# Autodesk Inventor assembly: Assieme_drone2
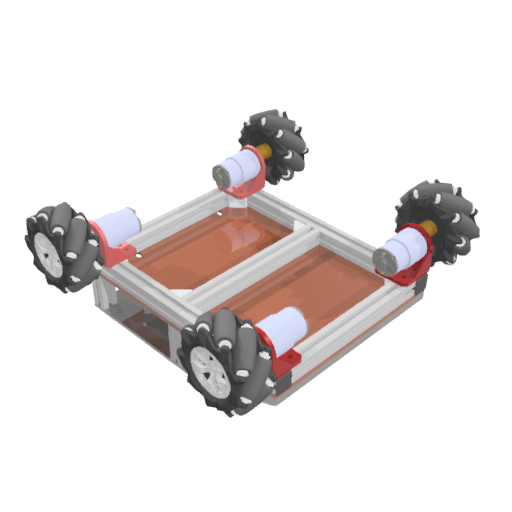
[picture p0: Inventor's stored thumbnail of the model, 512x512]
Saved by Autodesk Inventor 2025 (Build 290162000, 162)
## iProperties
Created: 2025-05
Part Number: Assieme_drone2
Document SubType Name: Assembly
Designer: R5800u
Author: R5800u
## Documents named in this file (28)
- C:\Users\R5800u\Desktop\drone_v2\Assieme_drone2.iam
- C:\Users\R5800u\Desktop\drone_v2\tslot-20x20-1.ipt
- C:\Users\R5800u\Desktop\drone_v2\tslot-20x20-1_MIR.ipt
- C:\Users\R5800u\Desktop\drone_v2\tslot-20x20-2.ipt
- C:\Users\R5800u\Desktop\drone_v2\SNSD20x20.ipt
- C:\Users\R5800u\Desktop\drone_v2\SNSD20x20_MIR.ipt
- C:\Users\R5800u\Desktop\drone_v2\tslot-20x20-3.ipt
- C:\Users\R5800u\Desktop\drone_v2\MM-JGB37 v4.ipt
- C:\Users\R5800u\Desktop\drone_v2\JGB37-520.ipt
- C:\Users\R5800u\Documents\Inventor\Content Center Files\R2025\it-IT\AS 1427(05)\AS 1427 - M4 x 10(5) II.ipt
- C:\Users\R5800u\Desktop\drone_v2\MM-JGB37 v4_MIR.ipt
- C:\Users\R5800u\Desktop\drone_v2\JGB37-520_MIR.ipt
- C:\Users\R5800u\Desktop\drone_v2\MM-JGB37 v4_MIR1.ipt
- C:\Users\R5800u\Desktop\drone_v2\JGB37-520_MIR1.ipt
- C:\Users\R5800u\Desktop\drone_v2\MM-JGB37 v4_MIR_MIR.ipt
- C:\Users\R5800u\Desktop\drone_v2\JGB37-520_MIR_MIR.ipt
- C:\Users\R5800u\Desktop\drone_v2\Mecanum wheel - right.ipt
- C:\Users\R5800u\Desktop\drone_v2\Mecanum wheel - left.ipt
- C:\Users\R5800u\Desktop\drone_v2\albero_ottonre_12x6.ipt
- C:\Users\R5800u\Desktop\drone_v2\tappi_tslot.ipt
- C:\Users\R5800u\Desktop\drone_v2\pianoA.ipt
- C:\Users\R5800u\Desktop\drone_v2\batteira_6V_LIFEPO4.ipt
- C:\Users\R5800u\Desktop\drone_v2\L298N.ipt
- C:\Users\R5800u\Desktop\drone_v2\ESP32-C3 Super Mini breakout expansion board module -Assembly.iam
- C:\Users\R5800u\Desktop\drone_v2\beetle ESP32-C3.iam
- C:\Users\R5800u\Desktop\jgb37\piano2.ipt
- C:\Users\R5800u\Desktop\jgb37\lato.ipt
- C:\Users\R5800u\Desktop\jgb37\lato2.ipt
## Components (48 placed, 27 different names)
1. tslot-20x20-1:1
2. tslot-20x20-1_MIR:1
3. tslot-20x20-2:1
4. tslot-20x20-2:2
5. SNSD20x20:1 — Allineato:14, Coincidente:22, Coincidente:23
6. SNSD20x20:2 — Allineato:13, Coincidente:20, Coincidente:21
7. SNSD20x20_MIR:1 — Allineato:15, Coincidente:24, Coincidente:27
8. SNSD20x20_MIR:2 — Allineato:16, Coincidente:25, Coincidente:26
9. tslot-20x20-2:3 — Allineato:17, Coincidente:28, Allineato:30, Allineato:32, Coincidente:30, Allineato:33, Coincidente:31
10. SNSD20x20_MIR:3 — Allineato:32, Coincidente:29, Coincidente:30
11. SNSD20x20:3 — Allineato:33, Coincidente:31, Coincidente:32
12. tslot-20x20-3:7 — Coincidente:70, Allineato:59, Allineato:62
13. MM-JGB37 v4:1
14. JGB37-520:1 — Rotazionale:1, Coincidente:43, Coincidente:44, Rigido:5
15. AS 1427 H - Metrico M4 x 10:1 — Coincidente:47
16. AS 1427 H - Metrico M4 x 10:2 — Coincidente:49
17. AS 1427 H - Metrico M4 x 10:3 — Rotazionale:2
18. MM-JGB37 v4_MIR:1 — Coincidente:50, Coincidente:51, Rotazionale:3, Coincidente:67, Allineato:53, Allineato:54
19. JGB37-520_MIR:1 — Coincidente:50, Coincidente:51, Rotazionale:3, Rigido:6
20. MM-JGB37 v4_MIR1:1 — Coincidente:52, Coincidente:53, Rotazionale:4, Coincidente:58, Coincidente:59, Allineato:48
21. JGB37-520_MIR1:1 — Coincidente:52, Coincidente:53, Rotazionale:4, Rigido:1
22. MM-JGB37 v4_MIR_MIR:1 — Coincidente:54, Coincidente:55, Rotazionale:5, Coincidente:68, Allineato:55, Allineato:56
23. JGB37-520_MIR_MIR:1 — Coincidente:54, Coincidente:55, Rotazionale:5, Rigido:7
24. Mecanum wheel - right:1 — Coincidente:60, Coincidente:64
25. Mecanum wheel - right:2 — Coincidente:62, Coincidente:63
26. Mecanum wheel - left:1 — Coincidente:56, Angolo:1, Coincidente:57
27. Mecanum wheel - left:2 — Coincidente:61, Coincidente:65
28. albero_ottonre_12x6:1 — Coincidente:56, Angolo:1, Coincidente:57, Rigido:1
29. albero_ottonre_12x6:2 — Coincidente:61, Coincidente:65, Rigido:5
30. albero_ottonre_12x6:3 — Coincidente:60, Coincidente:64, Rigido:6
31. albero_ottonre_12x6:4 — Coincidente:62, Coincidente:63, Rigido:7
32. tappi_tslot:1 — Allineato:51
33. tappi_tslot:2 — Rotazionale:6
34. pianoA:1 — Coincidente:69, Allineato:57, Allineato:58, Coincidente:70, Allineato:59, Allineato:60, Coincidente:71, Allineato:63, Coincidente:73, Rotazionale:7, Allineato:65, Coincidente:77, Allineato:83, Coincidente:78, Coincidente:79, Allineato:84, Allineato:85, Rotazionale:12, Rotazionale:13, Coincidente:81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
35. batteira_6V_LIFEPO4:1 — Coincidente:71, Allineato:63, Coincidente:72, Allineato:64
36. batteira_6V_LIFEPO4:2 — Coincidente:72, Allineato:64, Coincidente:73, Allineato:83, Coincidente:80
37. tslot-20x20-3:8 — Rotazionale:7, Allineato:65, Allineato:88
38. L298N:2 — Coincidente:79, Allineato:85, Allineato:86
39. L298N:3 — Coincidente:78, Allineato:84, Allineato:86, Allineato:87, Coincidente:80
40. ESP32-C3 Super Mini breakout expansion board module -Assembly:1 [sub-assembly] — Coincidente:77, Allineato:87
41. beetle ESP32-C3:1 [sub-assembly]
42. tslot-20x20-3:13 — Rotazionale:12
43. tslot-20x20-3:14 — Rotazionale:13
44. piano2:1 — Allineato:88, Allineato:89
45. lato:1 — Allineato:89, Allineato:91
46. lato2:1 — Coincidente:81, Allineato:90, Allineato:91
47. tappi_tslot:3 — Rigido:8
48. tappi_tslot:4 — Coincidente:82, Coincidente:83, Allineato:92
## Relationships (94: Mate 47, Flush 32, RevoluteJoint 9, WeldJoint 5, Angle 1)
- Allineato:13 [Flush]: SNSD20x20:2
- Coincidente:20 [Mate]: SNSD20x20:2
- Coincidente:21 [Mate]: SNSD20x20:2
- Allineato:14 [Flush]: SNSD20x20:1
- Coincidente:22 [Mate]: SNSD20x20:1
- Coincidente:23 [Mate]: SNSD20x20:1
- Allineato:15 [Flush]: SNSD20x20_MIR:1
- Allineato:16 [Flush]: SNSD20x20_MIR:2
- Coincidente:24 [Mate]: SNSD20x20_MIR:1
- Coincidente:25 [Mate]: SNSD20x20_MIR:2
- Coincidente:26 [Mate]: SNSD20x20_MIR:2
- Coincidente:27 [Mate]: SNSD20x20_MIR:1
- Allineato:17 [Flush]: tslot-20x20-2:3
- Coincidente:28 [Mate]: tslot-20x20-2:3
- Allineato:30 [Flush]: tslot-20x20-2:3
- Allineato:32 [Flush]: tslot-20x20-2:3 ↔ SNSD20x20_MIR:3
- Coincidente:29 [Mate]: SNSD20x20_MIR:3
- Coincidente:30 [Mate]: tslot-20x20-2:3 ↔ SNSD20x20_MIR:3
- Allineato:33 [Flush]: tslot-20x20-2:3 ↔ SNSD20x20:3
- Coincidente:31 [Mate]: tslot-20x20-2:3 ↔ SNSD20x20:3
- Coincidente:32 [Mate]: SNSD20x20:3
- Rotazionale:1 [RevoluteJoint]: JGB37-520:1
- Coincidente:43 [Mate]: JGB37-520:1
- Coincidente:44 [Mate]: JGB37-520:1
- Coincidente:47 [Mate]: AS 1427 H - Metrico M4 x 10:1
- Coincidente:49 [Mate]: AS 1427 H - Metrico M4 x 10:2
- Rotazionale:2 [RevoluteJoint]: AS 1427 H - Metrico M4 x 10:3
- Coincidente:50 [Mate]: MM-JGB37 v4_MIR:1 ↔ JGB37-520_MIR:1
- Coincidente:51 [Mate]: MM-JGB37 v4_MIR:1 ↔ JGB37-520_MIR:1
- Rotazionale:3 [RevoluteJoint]: MM-JGB37 v4_MIR:1 ↔ JGB37-520_MIR:1
- Coincidente:52 [Mate]: MM-JGB37 v4_MIR1:1 ↔ JGB37-520_MIR1:1
- Coincidente:53 [Mate]: MM-JGB37 v4_MIR1:1 ↔ JGB37-520_MIR1:1
- Coincidente:54 [Mate]: MM-JGB37 v4_MIR_MIR:1 ↔ JGB37-520_MIR_MIR:1
- Coincidente:55 [Mate]: MM-JGB37 v4_MIR_MIR:1 ↔ JGB37-520_MIR_MIR:1
- Rotazionale:4 [RevoluteJoint]: MM-JGB37 v4_MIR1:1 ↔ JGB37-520_MIR1:1
- Rotazionale:5 [RevoluteJoint]: MM-JGB37 v4_MIR_MIR:1 ↔ JGB37-520_MIR_MIR:1
- Coincidente:56 [Mate]: Mecanum wheel - left:1 ↔ albero_ottonre_12x6:1
- Angolo:1 [Angle]: Mecanum wheel - left:1 ↔ albero_ottonre_12x6:1
- Coincidente:57 [Mate]: Mecanum wheel - left:1 ↔ albero_ottonre_12x6:1
- Coincidente:58 [Mate]: MM-JGB37 v4_MIR1:1
- Coincidente:59 [Mate]: MM-JGB37 v4_MIR1:1
- Allineato:48 [Flush]: MM-JGB37 v4_MIR1:1
- Rigido:1 [WeldJoint]: JGB37-520_MIR1:1 ↔ albero_ottonre_12x6:1
- Coincidente:60 [Mate]: Mecanum wheel - right:1 ↔ albero_ottonre_12x6:3
- Coincidente:61 [Mate]: Mecanum wheel - left:2 ↔ albero_ottonre_12x6:2
- Coincidente:62 [Mate]: Mecanum wheel - right:2 ↔ albero_ottonre_12x6:4
- Coincidente:63 [Mate]: Mecanum wheel - right:2 ↔ albero_ottonre_12x6:4
- Coincidente:64 [Mate]: Mecanum wheel - right:1 ↔ albero_ottonre_12x6:3
- Coincidente:65 [Mate]: Mecanum wheel - left:2 ↔ albero_ottonre_12x6:2
- Allineato:51 [Flush]: tappi_tslot:1
- Rotazionale:6 [RevoluteJoint]: tappi_tslot:2
- Rigido:5 [WeldJoint]: JGB37-520:1 ↔ albero_ottonre_12x6:2
- Coincidente:67 [Mate]: MM-JGB37 v4_MIR:1
- Allineato:53 [Flush]: MM-JGB37 v4_MIR:1
- Allineato:54 [Flush]: MM-JGB37 v4_MIR:1
- Rigido:6 [WeldJoint]: JGB37-520_MIR:1 ↔ albero_ottonre_12x6:3
- Coincidente:68 [Mate]: MM-JGB37 v4_MIR_MIR:1
- Allineato:55 [Flush]: MM-JGB37 v4_MIR_MIR:1
- Allineato:56 [Flush]: MM-JGB37 v4_MIR_MIR:1
- Rigido:7 [WeldJoint]: JGB37-520_MIR_MIR:1 ↔ albero_ottonre_12x6:4
- Coincidente:69 [Mate]: pianoA:1
- Allineato:57 [Flush]: pianoA:1
- Allineato:58 [Flush]: pianoA:1
- Coincidente:70 [Mate]: tslot-20x20-3:7 ↔ pianoA:1
- Allineato:59 [Flush]: tslot-20x20-3:7 ↔ pianoA:1
- Allineato:60 [Flush]: pianoA:1
- Allineato:62 [Flush]: tslot-20x20-3:7
- Coincidente:71 [Mate]: pianoA:1 ↔ batteira_6V_LIFEPO4:1
- Allineato:63 [Flush]: pianoA:1 ↔ batteira_6V_LIFEPO4:1
- Coincidente:72 [Mate]: batteira_6V_LIFEPO4:1 ↔ batteira_6V_LIFEPO4:2
- Allineato:64 [Flush]: batteira_6V_LIFEPO4:1 ↔ batteira_6V_LIFEPO4:2
- Coincidente:73 [Mate]: pianoA:1 ↔ batteira_6V_LIFEPO4:2
- Rotazionale:7 [RevoluteJoint]: pianoA:1 ↔ tslot-20x20-3:8
- Allineato:65 [Flush]: pianoA:1 ↔ tslot-20x20-3:8
- Coincidente:77 [Mate]: pianoA:1 ↔ ESP32-C3 Super Mini breakout expansion board module -Assembly:1
- Allineato:83 [Flush]: pianoA:1 ↔ batteira_6V_LIFEPO4:2
- Coincidente:78 [Mate]: pianoA:1 ↔ L298N:3
- Coincidente:79 [Mate]: pianoA:1 ↔ L298N:2
- Allineato:84 [Flush]: pianoA:1 ↔ L298N:3
- Allineato:85 [Flush]: pianoA:1 ↔ L298N:2
- Allineato:86 [Flush]: L298N:2 ↔ L298N:3
- Allineato:87 [Flush]: L298N:3 ↔ ESP32-C3 Super Mini breakout expansion board module -Assembly:1
- Coincidente:80 [Mate]: batteira_6V_LIFEPO4:2 ↔ L298N:3
- Rotazionale:12 [RevoluteJoint]: pianoA:1 ↔ tslot-20x20-3:13
- Rotazionale:13 [RevoluteJoint]: pianoA:1 ↔ tslot-20x20-3:14
- Allineato:88 [Flush]: tslot-20x20-3:8 ↔ piano2:1
- Allineato:89 [Flush]: piano2:1 ↔ lato:1
- Coincidente:81 [Mate]: pianoA:1 ↔ lato2:1
- Allineato:90 [Flush]: pianoA:1 ↔ lato2:1
- Allineato:91 [Flush]: lato:1 ↔ lato2:1
- Coincidente:82 [Mate]: tappi_tslot:4
- Coincidente:83 [Mate]: tappi_tslot:4
- Allineato:92 [Flush]: tappi_tslot:4
- Rigido:8 [WeldJoint]: tappi_tslot:3
